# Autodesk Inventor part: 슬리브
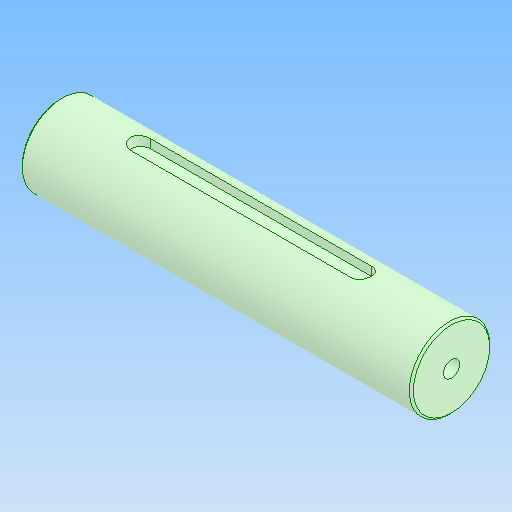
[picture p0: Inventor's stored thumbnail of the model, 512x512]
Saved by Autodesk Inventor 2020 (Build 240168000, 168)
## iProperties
Created: 2024-07
Part Number: 슬리브
Material: 강철, 탄소
Document SubType Name: Modeling
Designer: oem
Density: 7.85 g/cm^3
Appearance: 기본값
Author: jhkim
Sending System: Autodesk Inventor 2025
Preprocessor: ST-DEVELOPER v20
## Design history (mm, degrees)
feature "솔리드1"
node "솔리드2"
